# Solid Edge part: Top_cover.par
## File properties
Author: jmrobins
Template: Normal.par
Last saved by: rkriggs
Revision: 30
Application: Solid Edge
Density: 8470.000 kg/m^3
Accuracy: 0.990
Material: Brass, yellow brass
Face Style: Brass
Fill Style: ANSI33(Brass)
Virtual Style: Polished brass
Coef. of Thermal Exp: 2e-05
Thermal Conductivity: 116.0
Specific Heat: 377.0
Modulus of Elasticity: 103421355000.0
Poission's Ratio: 0.32
Yield Stress: 413685420.0
Ultimate Stress: 510212018.0
Elongation: 0.0
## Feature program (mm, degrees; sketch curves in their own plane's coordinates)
pattern "unnamed Pattern 1"
pattern "unnamed Pattern 2"
Other named dimensions: "Hole_5": Diameter = 15 mm
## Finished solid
Body 1: solid body, 35 faces, 94 edges, 56 vertices.
  Faces by surface: plane 18, cylinder 17
  Edges by curve: line 60, circle 26, ellipse 8
Bounding box of the edges (mm): 60.000 x 60.000 x 10.000, from (-30, -30, 0) to (30, 30, 10).
Cylindrical faces by radius (mm): R2 x4, R5 x4, R7.5 x1, R9.5 x4, R10 x4
Planar faces by outward normal: +x 1, +y 1, +z 5, -x 1, -y 1, -z 1, oblique 8
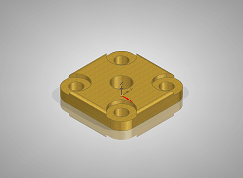
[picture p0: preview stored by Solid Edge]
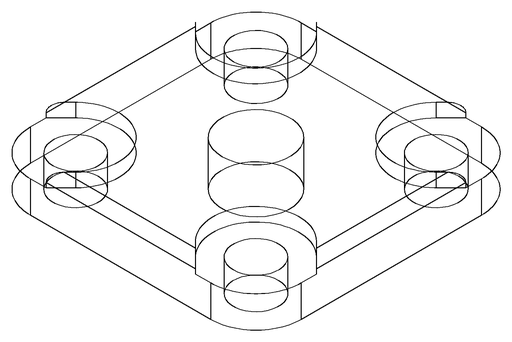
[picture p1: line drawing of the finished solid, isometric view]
